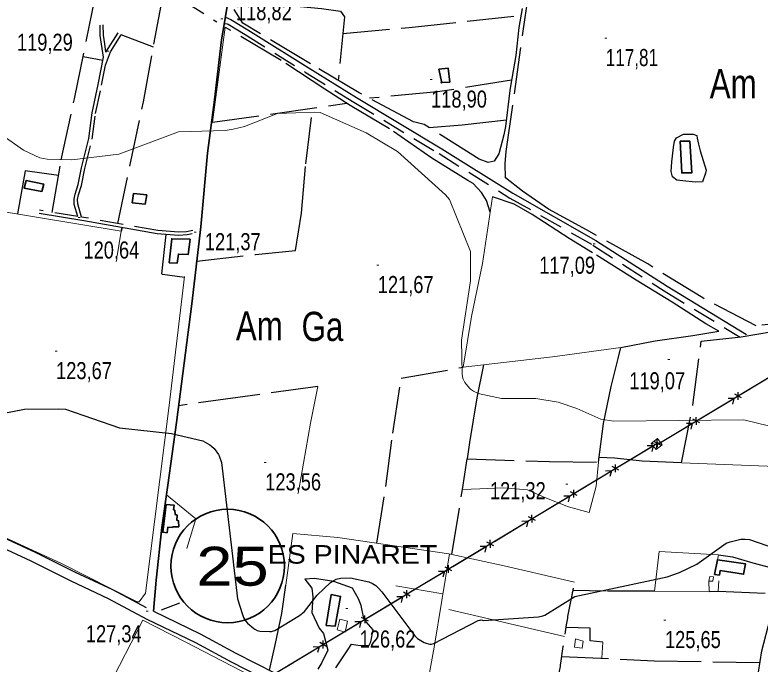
# Model space of a CAD drawing. Extents: x 483840 to 488445, y 4386047 to 4389027.
# Drawn here: x 484833.2 to 485215.3, y 4387140.8 to 4387473.9 of the extents above; entities that cross this region are included whole.
import ezdxf
from ezdxf.enums import TextEntityAlignment as Align

# ---------------------------------------------------------------- set-up
doc = ezdxf.new("R2010")
doc.units = 0
doc.header["$LTSCALE"] = 4
doc.linetypes.add('LONG_DASHED', pattern=[7.5, 6, -1.5])
doc.linetypes.add('MEDIUM_DASHED', pattern=[4.5, 3, -1.5])
for name, color, linetype, lineweight in [('13', 7, 'Continuous', 25), ('25', 7, 'LONG_DASHED', 25), ('36', 7, 'Continuous', 25), ('38', 7, 'Continuous', 25), ('43', 7, 'Continuous', 25), ('47', 7, 'Continuous', 35), ('51', 7, 'Continuous', 13), ('6', 7, 'Continuous', 35), ('7', 7, 'Continuous', 13), ('8', 7, 'Continuous', 25), ('9', 7, 'Continuous', 13)]:
    doc.layers.add(name, color=color, linetype=linetype, lineweight=lineweight)
doc.layers.add('31', color=7, linetype='Continuous')
doc.layers.add('5', color=7, linetype='Continuous')

msp = doc.modelspace()

# ---------------------------------------------------------------- linework, layer by layer
at = {"layer": '25'}
for p, q in [((484904.23, 4387457.27), (484887.63, 4387463.7)), ((484878.25, 4387450.41), (484868.13, 4387452.44)), ((484934.54, 4387418.79), (485003.39, 4387428.57)), ((485019.25, 4387204.68), (485019.23, 4387204.7))]:
    msp.add_line(p, q, dxfattribs=at)
for points in [[(484852.28, 4387372.58), (484856.92, 4387399.54), (484863.76, 4387430.8), (484878.02, 4387501.4), (484886.96, 4387501.75), (484850.06, 4387523.65), (484801.5, 4387554.4), (484755.42, 4387581.97), (484718.14, 4387605.13), (484692.31, 4387620.53), (484674.97, 4387630.93)], [(484885.92, 4387366.89), (484899.09, 4387429.29), (484909.76, 4387487.39), (484936.79, 4387470.3)], [(485258.29, 4387319.7), (485240.09, 4387317.31), (485213.32, 4387314.41), (485185.96, 4387328.68), (485157.71, 4387346.09), (485126.4, 4387363.6), (485106.76, 4387374.27), (485093.45, 4387383.46), (485084.8, 4387390.21), (485084.56, 4387397.54), (485085.21, 4387403.77), (485089.44, 4387433.36), (485094.8, 4387472.61), (485097.04, 4387487.7)], [(484944.62, 4387479.48), (484972.17, 4387478.82), (484990.51, 4387477.2), (485000.22, 4387475.84), (485002.21, 4387472.88), (484998.99, 4387440.28)], [(485093.34, 4387477.2), (485091.54, 4387467.44), (485090.12, 4387453), (485087.35, 4387437.35), (485087.05, 4387435.17), (485084.83, 4387416.64), (485083.98, 4387412.31), (485081.33, 4387402.63), (485079.05, 4387398.87), (485075.84, 4387398.14), (485071.25, 4387399.89), (485043.14, 4387417.62), (485037.59, 4387419.02), (485009.75, 4387433.91), (484984.76, 4387448.69), (484950.17, 4387469.59), (484945.65, 4387476.67)], [(485001.38, 4387464.37), (485035.39, 4387467.37), (485092.69, 4387473.66)], [(485076.99, 4387372.71), (485075.1, 4387378.65), (485072.51, 4387382.81), (485068.22, 4387387.44), (485065.4, 4387388.89), (485047, 4387400.39), (485025.31, 4387415.4), (485005.17, 4387427.43), (484992.14, 4387435.74), (484969.77, 4387450.55), (484941.14, 4387467.45)], [(485087.89, 4387440.36), (485049.88, 4387434.32), (485015.04, 4387431.08)], [(484977.02, 4387352.94), (484980.19, 4387372.22), (484982.38, 4387397.5), (484985.95, 4387426.09)], [(485085.22, 4387419.82), (485062.56, 4387417.26), (485045.7, 4387416.01)], [(484855.54, 4387391.53), (484838.52, 4387393.8), (484834.51, 4387371.79)], [(485143.97, 4387303.25), (485161.48, 4387306.58), (485180.77, 4387309.42), (485194.2, 4387311.7), (485187.45, 4387315.43), (485170.33, 4387326.42), (485151.81, 4387337.84), (485129.46, 4387351.84), (485117.48, 4387359.15), (485098.51, 4387371.55), (485093.93, 4387374.08), (485089.26, 4387376.73), (485078.19, 4387380.6)], [(484888.02, 4387364.83), (484887.94, 4387363.72), (484888.19, 4387364.8), (484887.77, 4387362.97)], [(484920.12, 4387339.2), (484908.95, 4387340.77), (484908.48, 4387341.09), (484910.77, 4387361.27)], [(484926.47, 4387347.55), (484956.59, 4387350.93), (484977.02, 4387352.94)], [(485174.98, 4387244.02), (485180.81, 4387273.6), (485185.17, 4387306.48), (485205.62, 4387308.68), (485221.71, 4387311.48), (485252.39, 4387316.38), (485251.98, 4387314.37), (485248.15, 4387288.69), (485236.61, 4387241.67)], [(485073.56, 4387294.36), (485070.08, 4387277.35), (485066.37, 4387254.55), (485065.18, 4387246.07), (485107.37, 4387244.73), (485132.45, 4387244.34), (485134.97, 4387264.28), (485139.02, 4387283.28), (485142.51, 4387297.63), (485143.97, 4387303.25)], [(485018.88, 4387202.86), (485023.44, 4387231.95), (485027.02, 4387259.24), (485031.34, 4387287.53), (485063.16, 4387293.14)], [(484988.48, 4387283.16), (484951.21, 4387278.08), (484917.13, 4387273.36)], [(485174.98, 4387244.02), (485154.93, 4387244.85), (485140.73, 4387246.42), (485132.75, 4387246.75)], [(485057.21, 4387197.06), (485062.71, 4387230.46), (485065.18, 4387246.07)], [(485194.08, 4387196.85), (485201.17, 4387195.77), (485211.65, 4387192.75), (485223.93, 4387189.48), (485225.61, 4387192.86)], [(484997.83, 4387138.95), (485003.57, 4387147.66), (485005.89, 4387151.04), (485010.33, 4387150.28), (485014.83, 4387150.45), (485015.71, 4387152.23), (485016.92, 4387158.38), (485013.33, 4387162.47), (485011.89, 4387165.09), (485010.82, 4387170.94), (485009.36, 4387174.36), (485006.26, 4387179.82), (484996.76, 4387183.26), (484986.83, 4387184.7), (484981.94, 4387184.31), (484985.42, 4387179.81), (484986.05, 4387175.33), (484985.48, 4387167.24), (484989.27, 4387159.32), (484991.43, 4387156.49), (484993.7, 4387147.97), (484990.57, 4387141.65), (484988.59, 4387138.3)], [(484963.78, 4387137.66), (484966.84, 4387151.33), (484970.05, 4387166.71), (484972.16, 4387181.4)], [(485161.14, 4387178.17), (485136.38, 4387178.31), (485119.38, 4387178.52)], [(485189.21, 4387178.1), (485193.91, 4387178.21), (485221.13, 4387177.07)], [(485134.68, 4387152.01), (485128.17, 4387152.75), (485128.25, 4387159.19), (485115.84, 4387159.68)], [(485113.68, 4387144.75), (485161.1, 4387142.5), (485215.24, 4387141.66)]]:
    msp.add_lwpolyline(points, dxfattribs=at)
msp.add_lwpolyline([(485183.83, 4387407.63), (485184.61, 4387404.15), (485187.61, 4387394.14), (485187.35, 4387392.64), (485185.8, 4387388.31), (485182.08, 4387388.03), (485175.79, 4387388.74), (485172.6, 4387389.12), (485170.43, 4387390.85), (485169.76, 4387393.52), (485170.03, 4387398.56), (485170.88, 4387405.88), (485171.39, 4387409.1), (485172.41, 4387410.88), (485176.14, 4387412.72), (485176.74, 4387412.72), (485181.03, 4387412.66), (485182.93, 4387411.96), (485183.06, 4387410.55)], close=True, dxfattribs=at)
at = {"layer": '36'}
for points in [[(484660.3, 4387281.08), (484688, 4387267.44), (484716.6, 4387252.46), (484744.57, 4387237.87), (484765.96, 4387228.04), (484785.95, 4387219.5), (484804.94, 4387211.05), (484823.92, 4387201.9), (484841.33, 4387193.76), (484861.92, 4387183.47), (484880.95, 4387174.47), (484900.92, 4387163.88), (484925.9, 4387151.85), (484944.1, 4387141.99), (484964.47, 4387131.61)], [(484731.26, 4387250.54), (484746.8, 4387242.43), (484768.02, 4387232.68), (484785.12, 4387224.95), (484803.58, 4387216.58), (484824.62, 4387206.9), (484843.61, 4387198.29), (484864.14, 4387188.04), (484883.22, 4387179.01), (484900.49, 4387169.86)], [(484904.27, 4387167.9), (484928.21, 4387156.37), (484946.46, 4387146.48), (484966.73, 4387136.15)]]:
    msp.add_lwpolyline(points, dxfattribs=at)
at = {"layer": '38'}
msp.add_line((484879.88, 4387454.71), (484886.11, 4387464.65), dxfattribs=at)
at = {"layer": '38', "linetype": 'MEDIUM_DASHED'}
msp.add_line((484865.45, 4387370.45), (484845.84, 4387373.62), dxfattribs=at)
at = {"layer": '38'}
for points in [[(484941.19, 4387472.79), (484943.94, 4387471.56), (484952.68, 4387466.23), (484983.53, 4387446.97), (485008.44, 4387431.5), (485052.17, 4387405.09), (485088.53, 4387382.35), (485131.09, 4387358.17), (485167.67, 4387334.65), (485208.32, 4387309.93)], [(484878.59, 4387452.16), (484877.67, 4387458.79), (484877.01, 4387463.35), (484876.94, 4387468.68)], [(484865.45, 4387370.45), (484863.61, 4387376.67), (484863.56, 4387379.4), (484864.05, 4387381.94), (484865.67, 4387386.81), (484867.36, 4387395.39), (484871.04, 4387410.4), (484872.79, 4387423.56), (484875.89, 4387438.16), (484878.59, 4387452.16)], [(484924.19, 4387361.54), (484921.5, 4387360.97), (484917.32, 4387360.77), (484906.21, 4387361.61), (484868.53, 4387368.27), (484845.57, 4387371.98)], [(485188.25, 4387014.54), (485194.36, 4387043), (485201.48, 4387076.51), (485208.39, 4387112.85), (485214.45, 4387136.72), (485216.2, 4387147.63), (485220.52, 4387164.1), (485225.14, 4387190.18), (485225.46, 4387192.5), (485227, 4387196.19), (485229.51, 4387198.81), (485232.3, 4387200), (485239.48, 4387200.37), (485243.82, 4387199.78), (485254.95, 4387197.29), (485284.57, 4387190.75), (485297.27, 4387187.95), (485301.83, 4387187.79), (485305.79, 4387188.48), (485308.4, 4387189.83), (485311.39, 4387192.48), (485316.45, 4387198.49)]]:
    msp.add_lwpolyline(points, dxfattribs=at)
at = {"layer": '38', "linetype": 'MEDIUM_DASHED'}
for points in [[(484879.88, 4387454.71), (484879.27, 4387459.02), (484878.62, 4387463.48), (484878.55, 4387468.71)], [(484940.65, 4387469.47), (484942.07, 4387469.31), (484942.63, 4387469.06), (484951.2, 4387463.83), (484982.04, 4387444.58), (485006.97, 4387429.1), (485050.7, 4387402.69), (485087.09, 4387379.93), (485129.64, 4387355.76), (485166.18, 4387332.26), (485205.1, 4387308.59)], [(484867.34, 4387370.16), (484865.4, 4387376.94), (484865.35, 4387379.25), (484865.79, 4387381.49), (484867.41, 4387386.35), (484869.11, 4387395), (484872.8, 4387410.07), (484874.56, 4387423.26), (484877.65, 4387437.8), (484879.64, 4387448.15), (484882.15, 4387454.97), (484887.63, 4387463.7)], [(484924.4, 4387363.28), (484921.28, 4387362.62), (484917.34, 4387362.43), (484906.42, 4387363.26), (484867.34, 4387370.16)]]:
    msp.add_lwpolyline(points, dxfattribs=at)
at = {"layer": '38', "linetype": 'LONG_DASHED'}
msp.add_spline([(485100.14, 4387067.55), (485105.76, 4387094.65), (485108.05, 4387109.75), (485110.91, 4387128.01), (485113.17, 4387141.29), (485116.07, 4387161.02), (485118.64, 4387174.55), (485120.17, 4387182.77)], degree=3, dxfattribs=at)
at = {"layer": '43'}
for p, q in [((485206.23, 4387279.71), (485223.37, 4387290.03)), ((485184.81, 4387266.82), (485201.95, 4387277.13)), ((485201.95, 4387277.13), (485198.94, 4387277.08)), ((485201.95, 4387277.13), (485201.22, 4387274.22)), ((485205.84, 4387277.45), (485202.34, 4387279.38)), ((485204.13, 4387276.42), (485204.06, 4387280.41)), ((485184.42, 4387264.56), (485180.92, 4387266.49)), ((485182.71, 4387263.53), (485182.64, 4387267.52)), ((485163.39, 4387253.93), (485180.53, 4387264.24)), ((485180.53, 4387264.24), (485177.52, 4387264.19)), ((485180.53, 4387264.24), (485179.8, 4387261.33)), ((485164.38, 4387253.14), (485160.88, 4387255.08)), ((485162.66, 4387252.11), (485162.59, 4387256.11)), ((485143.35, 4387242.51), (485160.48, 4387252.83)), ((485160.48, 4387252.83), (485157.48, 4387252.77)), ((485160.48, 4387252.83), (485159.76, 4387249.92)), ((485141.25, 4387239.21), (485141.18, 4387243.21)), ((485121.94, 4387229.6), (485139.07, 4387239.93)), ((485139.07, 4387239.93), (485136.07, 4387239.87)), ((485139.07, 4387239.93), (485138.35, 4387237.02)), ((485142.96, 4387240.24), (485139.46, 4387242.17)), ((485121.55, 4387227.34), (485118.05, 4387229.27)), ((485119.84, 4387226.31), (485119.76, 4387230.3)), ((485100.52, 4387216.7), (485117.65, 4387227.02)), ((485117.65, 4387227.02), (485114.65, 4387226.97)), ((485117.65, 4387227.02), (485116.93, 4387224.11)), ((485100.14, 4387214.44), (485096.64, 4387216.37)), ((485098.42, 4387213.4), (485098.35, 4387217.4)), ((485079.11, 4387203.8), (485096.24, 4387214.12)), ((485096.24, 4387214.12), (485093.24, 4387214.06)), ((485096.24, 4387214.12), (485095.52, 4387211.21)), ((485077.01, 4387200.5), (485076.94, 4387204.5)), ((485057.7, 4387190.89), (485074.83, 4387201.22)), ((485074.83, 4387201.22), (485071.83, 4387201.16)), ((485074.83, 4387201.22), (485074.11, 4387198.31)), ((485078.72, 4387201.53), (485075.23, 4387203.46)), ((485057.31, 4387188.63), (485053.81, 4387190.56)), ((485055.6, 4387187.6), (485055.53, 4387191.59)), ((485036.28, 4387177.99), (485053.42, 4387188.31)), ((485053.42, 4387188.31), (485050.41, 4387188.26)), ((485053.42, 4387188.31), (485052.69, 4387185.4)), ((485034.19, 4387174.69), (485034.11, 4387178.69)), ((485014.87, 4387165.09), (485032, 4387175.41)), ((485032, 4387175.41), (485029, 4387175.35)), ((485032, 4387175.41), (485031.28, 4387172.5)), ((485035.9, 4387175.73), (485032.4, 4387177.66)), ((484993.46, 4387152.19), (485010.59, 4387162.51)), ((485010.59, 4387162.51), (485007.59, 4387162.45)), ((485010.59, 4387162.51), (485009.87, 4387159.6)), ((485014.49, 4387162.82), (485010.99, 4387164.75)), ((485012.77, 4387161.79), (485012.7, 4387165.79)), ((484993.07, 4387149.92), (484989.57, 4387151.85)), ((484991.36, 4387148.89), (484991.29, 4387152.88)), ((484972.05, 4387139.28), (484989.18, 4387149.6)), ((484989.18, 4387149.6), (484986.18, 4387149.55)), ((484989.18, 4387149.6), (484988.45, 4387146.69))]:
    msp.add_line(p, q, dxfattribs=at)
at = {"layer": '43', "lineweight": 13}
for p, q in [((485162.72, 4387256.53), (485161.99, 4387250.89)), ((485159.53, 4387254.05), (485165.18, 4387253.37))]:
    msp.add_line(p, q, dxfattribs=at)
at = {"layer": '43'}
for points in [[(485163.39, 4387253.93), (485478.99, 4387443.87), (485790.32, 4387631.98)], [(484653.39, 4386941.6), (484915.42, 4387105.16), (485163.22, 4387254.48)]]:
    msp.add_lwpolyline(points, dxfattribs=at)
at = {"layer": '43', "lineweight": 13}
msp.add_lwpolyline([(485159.53, 4387254.05), (485162.72, 4387256.53), (485165.18, 4387253.37), (485161.99, 4387250.89)], close=True, dxfattribs=at)
at = {"layer": '47'}
for points in [[(485050.53, 4387445.98), (485055.38, 4387446.56), (485056.2, 4387439.43), (485051.78, 4387439.17), (485052.1, 4387439)], [(485174.4, 4387409.17), (485175.14, 4387392.8), (485180.33, 4387392.81), (485179.24, 4387409.11)], [(484838.94, 4387388.98), (484848.03, 4387387.11), (484846.97, 4387383.28), (484837.89, 4387385.05)], [(484900.81, 4387381.51), (484900.03, 4387376.8), (484893.37, 4387377.53), (484894.06, 4387382.3)], [(484912.23, 4387346.65), (484913.67, 4387359.07), (484923.04, 4387358.81), (484922.11, 4387350.97), (484917.03, 4387351.16), (484916.48, 4387346.59)], [(484910.72, 4387222.68), (484909.01, 4387208.46), (484911.25, 4387208.22), (484911.61, 4387211.02), (484913.81, 4387210.85), (484914.15, 4387211.32), (484917.2, 4387211.28), (484917.17, 4387214.27), (484916.26, 4387214.59), (484916.36, 4387217.28), (484915.4, 4387217.56), (484915.2, 4387219.78), (484914.61, 4387219.99), (484914.92, 4387222.28)], [(485192.04, 4387186.75), (485193.42, 4387194.35), (485207.9, 4387192.23), (485206.9, 4387186.94), (485194.84, 4387188.8), (485194.5, 4387186.47)], [(484995.44, 4387176.6), (484992.85, 4387160.65), (484997.42, 4387160.27), (485000.18, 4387175.52)]]:
    msp.add_lwpolyline(points, close=True, dxfattribs=at)
at = {"layer": '47', "lineweight": 13}
for points in [[(485191.53, 4387185.59), (485191.06, 4387183.35), (485189.12, 4387183.39), (485189.59, 4387185.83)], [(485003.78, 4387162.89), (485002.55, 4387157.12), (484998.54, 4387158.44), (484999.87, 4387163.91)], [(485124.54, 4387152.51), (485124.05, 4387149.07), (485120.12, 4387149.54), (485120.75, 4387153.85)]]:
    msp.add_lwpolyline(points, close=True, dxfattribs=at)
at = {"layer": '51'}
for p, q in [((484940.99, 4387467.66), (484934.54, 4387418.79)), ((484972.16, 4387181.4), (484975.74, 4387207.75)), ((485189.12, 4387183.39), (485189.21, 4387178.1)), ((485193.91, 4387178.21), (485194.18, 4387183.61)), ((485052.68, 4387176.83), (485028.55, 4387180.93)), ((485055.76, 4387168.88), (485115.1, 4387155.02)), ((485134.68, 4387152.01), (485134.26, 4387143.78))]:
    msp.add_line(p, q, dxfattribs=at)
for points in [[(484618.88, 4387407.44), (484887.77, 4387362.97), (484885.71, 4387350.31)], [(485078.19, 4387380.6), (485072.94, 4387346.37), (485067.27, 4387319.19), (485063.16, 4387293.14), (485108.86, 4387298.49), (485143.97, 4387303.25)], [(484920.16, 4387339.61), (484912.24, 4387273.42), (484900.1, 4387177.21), (484896.9, 4387172.79), (484895.92, 4387172.81), (484857.06, 4387192.51), (484776.86, 4387229.2), (484776.85, 4387233.96), (484777.19, 4387236.41)], [(484978.85, 4387230.27), (484984.81, 4387264.44), (484988.48, 4387283.16)], [(485132.45, 4387244.34), (485131.3, 4387232.12), (485127.66, 4387218.58), (485117.09, 4387221.58), (485104.98, 4387226.26), (485096.09, 4387230.22), (485083.69, 4387231.19), (485071.65, 4387230.75), (485062.71, 4387230.46)], [(485228.12, 4387203.02), (485236.61, 4387241.67), (485174.98, 4387244.02)], [(484910.94, 4387227.61), (484925.99, 4387215.33), (484921.29, 4387200.15)], [(485120.17, 4387182.77), (485084.12, 4387191.25), (485055.7, 4387197.38), (484998.86, 4387205.83), (484975.74, 4387207.75)], [(485056.04, 4387197.31), (485048.18, 4387149.53), (485039.89, 4387103.37), (485097.76, 4387068.96)], [(485189.21, 4387178.1), (485161.14, 4387178.17), (485163.53, 4387198.52), (485194.08, 4387196.85), (485193.42, 4387194.35)], [(484980.61, 4387121.81), (484958.86, 4387132.33), (484920.47, 4387152.2), (484898.75, 4387163.33), (484880.88, 4387128.52), (484851.17, 4387073.15), (484840.62, 4387053.24)]]:
    msp.add_lwpolyline(points, dxfattribs=at)
at = {"layer": '6', "lineweight": 25}
msp.add_line((484908.34, 4387168.72), (484917.75, 4387172.24), dxfattribs=at)
at = {"layer": '6'}
msp.add_lwpolyline([(484904.27, 4387167.9), (484905.66, 4387183.86), (484908.57, 4387210.82), (484911.66, 4387232.66), (484916.02, 4387264.71), (484923.85, 4387325.72), (484928.6, 4387365.22), (484931.97, 4387402.9), (484935.53, 4387430.32), (484939.12, 4387461.07), (484940.92, 4387470.98), (484942.02, 4387478.39)], dxfattribs=at)
msp.add_circle((484942.32, 4387191.13), 29.1, dxfattribs=at)
at = {"layer": '7'}
for p, q in [((484938.86, 4387471.79), (484939.86, 4387471.79)), ((485135.67, 4387461.99), (485136.67, 4387461.99)), ((484880.3, 4387455.22), (484881.3, 4387455.22)), ((485046.12, 4387440.68), (485047.12, 4387440.68)), ((484865.63, 4387369.93), (484866.63, 4387369.93)), ((484925.13, 4387362.47), (484926.13, 4387362.47)), ((485129.78, 4387356.44), (485130.78, 4387356.44)), ((485018.78, 4387345.55), (485019.78, 4387345.55)), ((484853.81, 4387301.37), (484854.81, 4387301.37)), ((485167.97, 4387297.16), (485168.97, 4387297.16)), ((484961.06, 4387244.32), (484962.06, 4387244.32)), ((485115.75, 4387233.14), (485116.75, 4387233.14)), ((484900.56, 4387168.05), (484901.56, 4387168.05)), ((485002.85, 4387169.33), (485003.85, 4387169.33)), ((485166.06, 4387163.41), (485167.06, 4387163.41))]:
    msp.add_line(p, q, dxfattribs=at)
at = {"layer": '8'}
for points in [[(484826.66, 4387269.38), (484838.13, 4387271.64), (484855.47, 4387271.75), (484859.18, 4387271.59), (484886.84, 4387261.99), (484913.57, 4387259.11), (484929.59, 4387255.28), (484933.2, 4387253.34), (484934.08, 4387252.69), (484935.41, 4387251.39), (484937.57, 4387248.29), (484937.94, 4387247.61), (484939.13, 4387244.28), (484947.36, 4387174.38), (484949.85, 4387166.2), (484950.43, 4387164.79), (484951.45, 4387163.01), (484952.42, 4387161.79), (484955.72, 4387159.03), (484956.29, 4387158.66), (484957.5, 4387158.07), (484958.88, 4387157.67), (484963.93, 4387157.49), (484964.82, 4387157.58), (484965.89, 4387157.81), (484966.57, 4387158.03), (484979.18, 4387165.73), (484981.64, 4387167.78), (484988.26, 4387176.17), (484994.98, 4387182.68), (484996.73, 4387183.79), (484997.97, 4387184.38), (484998.66, 4387184.63), (485000.29, 4387184.89), (485005.31, 4387185.07), (485014.72, 4387182.98), (485016.57, 4387182.15), (485018.25, 4387181.1), (485019.73, 4387179.85), (485021.41, 4387177.96), (485038.27, 4387155.26), (485039.7, 4387154.01), (485043.14, 4387151.92), (485044.16, 4387151.48), (485045.25, 4387151.18), (485045.95, 4387151.1), (485046.91, 4387151.13), (485048.03, 4387151.33), (485070.78, 4387163.25), (485071.38, 4387163.4), (485071.71, 4387163.44), (485072.26, 4387163.45), (485073.07, 4387163.33), (485073.57, 4387163.2), (485101.65, 4387165.12), (485103.93, 4387165.55), (485104.93, 4387165.85)], [(485104.93, 4387165.85), (485120.38, 4387175.44), (485167.65, 4387185.61), (485173.97, 4387187.76), (485182.86, 4387192.17), (485197.96, 4387202.83), (485200.02, 4387203.62), (485205.51, 4387204.89), (485207.68, 4387204.95), (485209.96, 4387204.73), (485227.15, 4387198.68), (485246.33, 4387188.54), (485249.24, 4387186.65), (485255.17, 4387181.19), (485270.35, 4387160.09), (485276.65, 4387148.15), (485286.93, 4387132.12)]]:
    msp.add_lwpolyline(points, dxfattribs=at)
at = {"layer": '9'}
for points in [[(485066.84, 4387281.84), (485066.25, 4387282.41), (485064.01, 4387285.26), (485063.12, 4387287), (485062.72, 4387288.15), (485062.53, 4387289.71), (485062.16, 4387307.05), (485066.77, 4387337.39), (485066.77, 4387352.44), (485056.01, 4387379.17), (485053.97, 4387381.62), (485029.44, 4387403.77), (485013.36, 4387413.32), (484989.71, 4387423.76), (484986.7, 4387424.04), (484967.95, 4387423.27), (484951.01, 4387416.64), (484945.18, 4387415.19), (484940.97, 4387414.63), (484917.1, 4387413.97), (484886.49, 4387402.42), (484862.48, 4387399.59), (484849.67, 4387399.89), (484846.03, 4387400.59), (484837.64, 4387404.43), (484818.29, 4387418.07)], [(485309.51, 4387241.13), (485207.05, 4387266.15), (485140.31, 4387265.38), (485133.66, 4387266.48), (485121.37, 4387271.93), (485111.77, 4387275.14), (485100.29, 4387277.03), (485082.73, 4387277.09), (485070.8, 4387279.67), (485068.29, 4387280.79), (485066.84, 4387281.84)]]:
    msp.add_lwpolyline(points, dxfattribs=at)

# ---------------------------------------------------------------- texts
at = {"layer": '13', "width": 1.25}
msp.add_text('25', height=20, dxfattribs=at).set_placement((484944.78, 4387181.04), align=Align.CENTER)
at = {"layer": '31', "width": 0.8}
for s, p in [('Am', (485201.55, 4387431.1)), ('Am', (484958.54, 4387306.85)), ('Ga', (484990.9, 4387306.57))]:
    msp.add_text(s, height=15, dxfattribs=at).set_placement(p, align=Align.CENTER)
at = {"layer": '5', "width": 1.15}
msp.add_text('ES PINARET', height=9.5, dxfattribs=at).set_placement((485049.75, 4387192.35), align=Align.RIGHT)
at = {"layer": '7'}
for s, width, p in [('118,82', 0.8, (484946.55, 4387471.17)), ('119,29', 0.8, (484834.26, 4387455.47)), ('117,81', 0.75, (485136.17, 4387447.62)), ('118,90', 0.8, (485046.62, 4387426.31)), ('121,37', 0.8, (484930.61, 4387353.17)), ('120,64', 0.8, (484868.36, 4387348.88)), ('117,09', 0.8, (485102.09, 4387341.08)), ('121,67', 0.8, (485019.28, 4387331.18)), ('123,67', 0.8, (484854.31, 4387287)), ('119,07', 0.8, (485148.25, 4387281.79)), ('123,56', 0.8, (484961.56, 4387229.95)), ('121,32', 0.8, (485076.79, 4387225.41)), ('127,34', 0.8, (484869.56, 4387152.02)), ('126,62', 0.8, (485009.98, 4387149.31)), ('125,65', 0.8, (485166.56, 4387149.04))]:
    msp.add_text(s, height=8.75, dxfattribs=dict(at, width=width)).set_placement(p)

doc.saveas('drawing.dxf')
